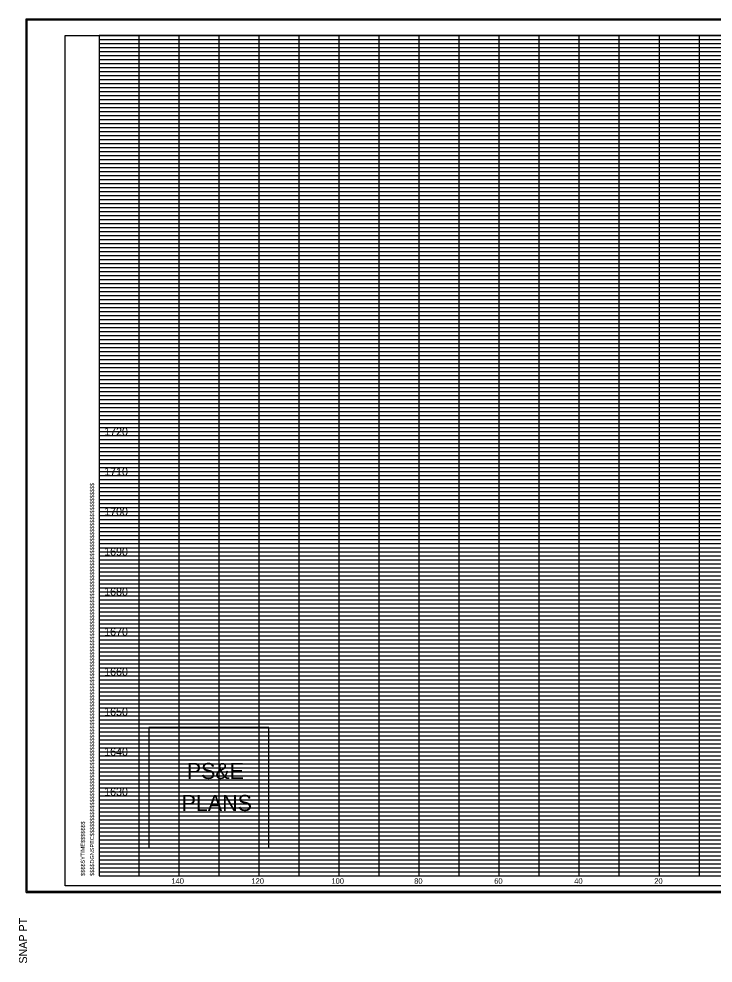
# Model space of a CAD drawing. Extents: x 980 to 2228, y 978 to 2394.
# Drawn here: x 979.9 to 1153.4, y 1788.2 to 2024.1 of the extents above; entities that cross this region are included whole.
import ezdxf

# ---------------------------------------------------------------- set-up
doc = ezdxf.new("R2010")
doc.units = 0
for name, color, linetype in [('DESIGN - SHEET - Corner Text', 7, 'Continuous'), ('DESIGN - SHEET - Light Grid', 7, 'Continuous'), ('DESIGN - SHEET - Linework', 7, 'Continuous'), ('DESIGN - SHEET - Plot Shape', 7, 'Continuous'), ('DESIGN - TYPICAL - Finished Grade and Subgrade', 7, 'Continuous')]:
    doc.layers.add(name, color=color, linetype=linetype)

# ---------------------------------------------------------------- blocks, each defined once
blk = doc.blocks.new('XSTSHT')
at = {"layer": 'DESIGN - SHEET - Light Grid'}
for p, q in [((0, 20.9), (8, 20.9)), ((0, 20.8), (8, 20.8)), ((8, 20.9), (16, 20.9)), ((8, 20.8), (16, 20.8)), ((0, 20.7), (8, 20.7)), ((0, 20.6), (8, 20.6)), ((8, 20.7), (16, 20.7)), ((8, 20.6), (16, 20.6)), ((0, 20.5), (8, 20.5)), ((0, 20.4), (8, 20.4)), ((0, 20.3), (8, 20.3)), ((8, 20.5), (16, 20.5)), ((8, 20.4), (16, 20.4)), ((8, 20.3), (16, 20.3)), ((0, 20.2), (8, 20.2)), ((0, 20.1), (8, 20.1)), ((8, 20.2), (16, 20.2)), ((8, 20.1), (16, 20.1)), ((0, 19.9), (8, 19.9)), ((8, 19.9), (16, 19.9)), ((0, 19.8), (8, 19.8)), ((0, 19.7), (8, 19.7)), ((0, 19.6), (8, 19.6)), ((8, 19.8), (16, 19.8)), ((8, 19.7), (16, 19.7)), ((8, 19.6), (16, 19.6)), ((0, 19.5), (8, 19.5)), ((0, 19.4), (8, 19.4)), ((8, 19.5), (16, 19.5)), ((8, 19.4), (16, 19.4)), ((0, 19.3), (8, 19.3)), ((0, 19.2), (8, 19.2)), ((8, 19.3), (16, 19.3)), ((8, 19.2), (16, 19.2)), ((0, 19.1), (8, 19.1)), ((0, 18.9), (8, 18.9)), ((8, 19.1), (16, 19.1)), ((8, 18.9), (16, 18.9)), ((0, 18.8), (8, 18.8)), ((0, 18.7), (8, 18.7)), ((8, 18.8), (16, 18.8)), ((8, 18.7), (16, 18.7)), ((0, 18.6), (8, 18.6)), ((0, 18.5), (8, 18.5)), ((8, 18.6), (16, 18.6)), ((8, 18.5), (16, 18.5)), ((0, 18.4), (8, 18.4)), ((0, 18.3), (8, 18.3)), ((0, 18.2), (8, 18.2)), ((8, 18.4), (16, 18.4)), ((8, 18.3), (16, 18.3)), ((8, 18.2), (16, 18.2)), ((0, 18.1), (8, 18.1)), ((8, 18.1), (16, 18.1)), ((0, 17.9), (8, 17.9)), ((0, 17.8), (8, 17.8)), ((0, 17.7), (8, 17.7)), ((8, 17.9), (16, 17.9)), ((8, 17.8), (16, 17.8)), ((8, 17.7), (16, 17.7)), ((0, 17.6), (8, 17.6)), ((0, 17.5), (8, 17.5)), ((8, 17.6), (16, 17.6)), ((8, 17.5), (16, 17.5)), ((0, 17.4), (8, 17.4)), ((0, 17.3), (8, 17.3)), ((8, 17.4), (16, 17.4)), ((8, 17.3), (16, 17.3)), ((0, 17.2), (8, 17.2)), ((0, 17.1), (8, 17.1)), ((8, 17.2), (16, 17.2)), ((8, 17.1), (16, 17.1)), ((0, 16.9), (8, 16.9)), ((0, 16.8), (8, 16.8)), ((8, 16.9), (16, 16.9)), ((8, 16.8), (16, 16.8)), ((0, 16.7), (8, 16.7)), ((0, 16.6), (8, 16.6)), ((8, 16.7), (16, 16.7)), ((8, 16.6), (16, 16.6)), ((0, 16.5), (8, 16.5)), ((0, 16.4), (8, 16.4)), ((0, 16.3), (8, 16.3)), ((8, 16.5), (16, 16.5)), ((8, 16.4), (16, 16.4)), ((8, 16.3), (16, 16.3)), ((0, 16.2), (8, 16.2)), ((0, 16.1), (8, 16.1)), ((8, 16.2), (16, 16.2)), ((8, 16.1), (16, 16.1)), ((0, 15.9), (8, 15.9)), ((8, 15.9), (16, 15.9)), ((0, 15.8), (8, 15.8)), ((0, 15.7), (8, 15.7)), ((0, 15.6), (8, 15.6)), ((8, 15.8), (16, 15.8)), ((8, 15.7), (16, 15.7)), ((8, 15.6), (16, 15.6)), ((0, 15.5), (8, 15.5)), ((0, 15.4), (8, 15.4)), ((8, 15.5), (16, 15.5)), ((8, 15.4), (16, 15.4)), ((0, 15.3), (8, 15.3)), ((0, 15.2), (8, 15.2)), ((8, 15.3), (16, 15.3)), ((8, 15.2), (16, 15.2)), ((0, 15.1), (8, 15.1)), ((0, 14.9), (8, 14.9)), ((8, 15.1), (16, 15.1)), ((8, 14.9), (16, 14.9)), ((0, 14.8), (8, 14.8)), ((0, 14.7), (8, 14.7)), ((8, 14.8), (16, 14.8)), ((8, 14.7), (16, 14.7)), ((0, 14.6), (8, 14.6)), ((0, 14.5), (8, 14.5)), ((0, 14.4), (8, 14.4)), ((8, 14.6), (16, 14.6)), ((8, 14.5), (16, 14.5)), ((8, 14.4), (16, 14.4)), ((0, 14.3), (8, 14.3)), ((0, 14.2), (8, 14.2)), ((8, 14.3), (16, 14.3)), ((8, 14.2), (16, 14.2)), ((0, 14.1), (8, 14.1)), ((8, 14.1), (16, 14.1)), ((0, 13.9), (8, 13.9)), ((0, 13.8), (8, 13.8)), ((0, 13.7), (8, 13.7)), ((8, 13.9), (16, 13.9)), ((8, 13.8), (16, 13.8)), ((8, 13.7), (16, 13.7)), ((0, 13.6), (8, 13.6)), ((0, 13.5), (8, 13.5)), ((8, 13.6), (16, 13.6)), ((8, 13.5), (16, 13.5)), ((0, 13.4), (8, 13.4)), ((0, 13.3), (8, 13.3)), ((8, 13.4), (16, 13.4)), ((8, 13.3), (16, 13.3)), ((0, 13.2), (8, 13.2)), ((0, 13.1), (8, 13.1)), ((8, 13.2), (16, 13.2)), ((8, 13.1), (16, 13.1)), ((0, 12.9), (8, 12.9)), ((0, 12.8), (8, 12.8)), ((8, 12.9), (16, 12.9)), ((8, 12.8), (16, 12.8)), ((0, 12.7), (8, 12.7)), ((0, 12.6), (8, 12.6)), ((8, 12.7), (16, 12.7)), ((8, 12.6), (16, 12.6)), ((0, 12.5), (8, 12.5)), ((0, 12.4), (8, 12.4)), ((0, 12.3), (8, 12.3)), ((8, 12.5), (16, 12.5)), ((8, 12.4), (16, 12.4)), ((8, 12.3), (16, 12.3)), ((0, 12.2), (8, 12.2)), ((0, 12.1), (8, 12.1)), ((8, 12.2), (16, 12.2)), ((8, 12.1), (16, 12.1)), ((0, 11.9), (8, 11.9)), ((0, 11.8), (8, 11.8)), ((8, 11.9), (16, 11.9)), ((8, 11.8), (16, 11.8)), ((0, 11.7), (8, 11.7)), ((0, 11.6), (8, 11.6)), ((8, 11.7), (16, 11.7)), ((8, 11.6), (16, 11.6)), ((0, 11.5), (8, 11.5)), ((0, 11.4), (8, 11.4)), ((8, 11.5), (16, 11.5)), ((8, 11.4), (16, 11.4)), ((0, 11.3), (8, 11.3)), ((0, 11.2), (8, 11.2)), ((0, 11.1), (8, 11.1)), ((8, 11.3), (16, 11.3)), ((8, 11.2), (16, 11.2)), ((8, 11.1), (16, 11.1)), ((0, 10.9), (8, 10.9)), ((8, 10.9), (16, 10.9)), ((0, 10.8), (8, 10.8)), ((0, 10.7), (8, 10.7)), ((8, 10.8), (16, 10.8)), ((8, 10.7), (16, 10.7)), ((0, 10.6), (8, 10.6)), ((0, 10.5), (8, 10.5)), ((0, 10.4), (8, 10.4)), ((8, 10.6), (16, 10.6)), ((8, 10.5), (16, 10.5)), ((8, 10.4), (16, 10.4)), ((0, 10.3), (8, 10.3)), ((0, 10.2), (8, 10.2)), ((8, 10.3), (16, 10.3)), ((8, 10.2), (16, 10.2)), ((0, 10.1), (8, 10.1)), ((8, 10.1), (16, 10.1)), ((0, 9.9), (8, 9.9)), ((0, 9.8), (8, 9.8)), ((0, 9.7), (8, 9.7)), ((8, 9.9), (16, 9.9)), ((8, 9.8), (16, 9.8)), ((8, 9.7), (16, 9.7)), ((0, 9.6), (8, 9.6)), ((0, 9.5), (8, 9.5)), ((8, 9.6), (16, 9.6)), ((8, 9.5), (16, 9.5)), ((0, 9.4), (8, 9.4)), ((0, 9.3), (8, 9.3)), ((8, 9.4), (16, 9.4)), ((8, 9.3), (16, 9.3)), ((0, 9.2), (8, 9.2)), ((0, 9.1), (8, 9.1)), ((8, 9.2), (16, 9.2)), ((8, 9.1), (16, 9.1)), ((0, 8.9), (8, 8.9)), ((0, 8.8), (8, 8.8)), ((8, 8.9), (16, 8.9)), ((8, 8.8), (16, 8.8)), ((0, 8.7), (8, 8.7)), ((0, 8.6), (8, 8.6)), ((0, 8.5), (8, 8.5)), ((8, 8.7), (16, 8.7)), ((8, 8.6), (16, 8.6)), ((8, 8.5), (16, 8.5)), ((0, 8.4), (8, 8.4)), ((0, 8.3), (8, 8.3)), ((8, 8.4), (16, 8.4)), ((8, 8.3), (16, 8.3)), ((0, 8.2), (8, 8.2)), ((0, 8.1), (8, 8.1)), ((8, 8.2), (16, 8.2)), ((8, 8.1), (16, 8.1)), ((0, 7.9), (8, 7.9)), ((0, 7.8), (8, 7.8)), ((8, 7.9), (16, 7.9)), ((8, 7.8), (16, 7.8)), ((0, 7.7), (8, 7.7)), ((0, 7.6), (8, 7.6)), ((8, 7.7), (16, 7.7)), ((8, 7.6), (16, 7.6)), ((0, 7.5), (8, 7.5)), ((0, 7.4), (8, 7.4)), ((8, 7.5), (16, 7.5)), ((8, 7.4), (16, 7.4)), ((0, 7.3), (8, 7.3)), ((0, 7.2), (8, 7.2)), ((0, 7.1), (8, 7.1)), ((8, 7.3), (16, 7.3)), ((8, 7.2), (16, 7.2)), ((8, 7.1), (16, 7.1)), ((0, 6.9), (8, 6.9)), ((8, 6.9), (16, 6.9)), ((0, 6.8), (8, 6.8)), ((0, 6.7), (8, 6.7)), ((8, 6.8), (16, 6.8)), ((8, 6.7), (16, 6.7)), ((0, 6.6), (8, 6.6)), ((0, 6.5), (8, 6.5)), ((0, 6.4), (8, 6.4)), ((8, 6.6), (16, 6.6)), ((8, 6.5), (16, 6.5)), ((8, 6.4), (16, 6.4)), ((0, 6.3), (8, 6.3)), ((0, 6.2), (8, 6.2)), ((8, 6.3), (16, 6.3)), ((8, 6.2), (16, 6.2)), ((0, 6.1), (8, 6.1)), ((0, 5.9), (8, 5.9)), ((8, 6.1), (16, 6.1)), ((8, 5.9), (16, 5.9)), ((0, 5.8), (8, 5.8)), ((0, 5.7), (8, 5.7)), ((8, 5.8), (16, 5.8)), ((8, 5.7), (16, 5.7)), ((0, 5.6), (8, 5.6)), ((0, 5.5), (8, 5.5)), ((8, 5.6), (16, 5.6)), ((8, 5.5), (16, 5.5)), ((0, 5.4), (8, 5.4)), ((0, 5.3), (8, 5.3)), ((0, 5.2), (8, 5.2)), ((8, 5.4), (16, 5.4)), ((8, 5.3), (16, 5.3)), ((8, 5.2), (16, 5.2)), ((0, 5.1), (8, 5.1)), ((8, 5.1), (16, 5.1)), ((0, 4.9), (8, 4.9)), ((0, 4.8), (8, 4.8)), ((8, 4.9), (16, 4.9)), ((8, 4.8), (16, 4.8)), ((0, 4.7), (8, 4.7)), ((0, 4.6), (8, 4.6)), ((0, 4.5), (8, 4.5)), ((8, 4.7), (16, 4.7)), ((8, 4.6), (16, 4.6)), ((8, 4.5), (16, 4.5)), ((0, 4.4), (8, 4.4)), ((0, 4.3), (8, 4.3)), ((8, 4.4), (16, 4.4)), ((8, 4.3), (16, 4.3)), ((0, 4.2), (8, 4.2)), ((0, 4.1), (8, 4.1)), ((8, 4.2), (16, 4.2)), ((8, 4.1), (16, 4.1)), ((0, 3.9), (8, 3.9)), ((0, 3.8), (8, 3.8)), ((8, 3.9), (16, 3.9)), ((8, 3.8), (16, 3.8)), ((0, 3.7), (8, 3.7)), ((0, 3.6), (8, 3.6)), ((8, 3.7), (16, 3.7)), ((8, 3.6), (16, 3.6)), ((0, 3.5), (8, 3.5)), ((0, 3.4), (8, 3.4)), ((8, 3.5), (16, 3.5)), ((8, 3.4), (16, 3.4)), ((0, 3.3), (8, 3.3)), ((0, 3.2), (8, 3.2)), ((0, 3.1), (8, 3.1)), ((8, 3.3), (16, 3.3)), ((8, 3.2), (16, 3.2)), ((8, 3.1), (16, 3.1)), ((0, 2.9), (8, 2.9)), ((8, 2.9), (16, 2.9)), ((0, 2.8), (8, 2.8)), ((0, 2.7), (8, 2.7)), ((0, 2.6), (8, 2.6)), ((8, 2.8), (16, 2.8)), ((8, 2.7), (16, 2.7)), ((8, 2.6), (16, 2.6)), ((0, 2.5), (8, 2.5)), ((0, 2.4), (8, 2.4)), ((8, 2.5), (16, 2.5)), ((8, 2.4), (16, 2.4)), ((0, 2.3), (8, 2.3)), ((0, 2.2), (8, 2.2)), ((8, 2.3), (16, 2.3)), ((8, 2.2), (16, 2.2)), ((0, 2.1), (8, 2.1)), ((0, 1.9), (8, 1.9)), ((8, 2.1), (16, 2.1)), ((8, 1.9), (16, 1.9)), ((0, 1.8), (8, 1.8)), ((0, 1.7), (8, 1.7)), ((8, 1.8), (16, 1.8)), ((8, 1.7), (16, 1.7)), ((0, 1.6), (8, 1.6)), ((0, 1.5), (8, 1.5)), ((8, 1.6), (16, 1.6)), ((8, 1.5), (16, 1.5)), ((0, 1.4), (8, 1.4)), ((0, 1.3), (8, 1.3)), ((0, 1.2), (8, 1.2)), ((8, 1.4), (16, 1.4)), ((8, 1.3), (16, 1.3)), ((8, 1.2), (16, 1.2)), ((0, 1.1), (8, 1.1)), ((8, 1.1), (16, 1.1)), ((0, 0.9), (8, 0.9)), ((0, 0.8), (8, 0.8)), ((8, 0.9), (16, 0.9)), ((8, 0.8), (16, 0.8)), ((0, 0.7), (8, 0.7)), ((0, 0.6), (8, 0.6)), ((0, 0.5), (8, 0.5)), ((8, 0.7), (16, 0.7)), ((8, 0.6), (16, 0.6)), ((8, 0.5), (16, 0.5)), ((0, 0.4), (8, 0.4)), ((0, 0.3), (8, 0.3)), ((8, 0.4), (16, 0.4)), ((8, 0.3), (16, 0.3)), ((0, 0.2), (8, 0.2)), ((0, 0.1), (8, 0.1)), ((8, 0.2), (16, 0.2)), ((8, 0.1), (16, 0.1))]:
    blk.add_line(p, q, dxfattribs=at)
at = {"layer": 'DESIGN - SHEET - Linework'}
for p, q in [((-1.823, -0.414), (-1.823, 21.414)), ((-1.823, 21.414), (32.217, 21.414)), ((1, 0), (1, 21)), ((2, 0), (2, 21)), ((3, 0), (3, 21)), ((4, 0), (4, 21)), ((5, 0), (5, 21)), ((6, 0), (6, 21)), ((7, 0), (7, 21)), ((8, 0), (8, 21)), ((9, 0), (9, 21)), ((10, 0), (10, 21)), ((11, 0), (11, 21)), ((12, 0), (12, 21)), ((13, 0), (13, 21)), ((14, 0), (14, 21)), ((15, 0), (15, 21)), ((0, 20), (28, 20)), ((0, 19), (32, 19)), ((0, 18), (32, 18)), ((0, 17), (32, 17)), ((0, 16), (32, 16)), ((0, 15), (32, 15)), ((0, 14), (32, 14)), ((0, 13), (32, 13)), ((0, 12), (32, 12)), ((0, 11), (32, 11)), ((0, 10), (32, 10)), ((0, 9), (32, 9)), ((0, 8), (32, 8)), ((0, 7), (32, 7)), ((0, 6), (32, 6)), ((0, 5), (32, 5)), ((0, 4), (32, 4)), ((0, 3), (32, 3)), ((0, 2), (32, 2)), ((0, 1), (32, 1)), ((-1.823, -0.414), (32.217, -0.414))]:
    blk.add_line(p, q, dxfattribs=at)
blk.add_lwpolyline([(0, 21), (0, 0), (32, 0), (32, 21), (0, 21)], dxfattribs=at)
at = {"layer": 'DESIGN - SHEET - Plot Shape'}
for points in [[(-1.803, 21.394), (32.197, 21.394), (32.197, -0.394), (-1.803, -0.394)], [(-0.85, 21), (32, 21), (32, -0.25), (-0.85, -0.25)]]:
    blk.add_lwpolyline(points, close=True, dxfattribs=at)
at = {"layer": 'DESIGN - SHEET - Corner Text'}
for s, height, p in [('$$$$DGNSPEC$$$$$$$$$$$$$$$$$$$$$$$$$$$$$$$$$$$$$$$$$$$$$$$$$$$$$$$$$$$$$$$$$$$$$$$$$$$$$$$$$$$$$$$$$$$$$$$$$$$$$$$$$$$$$$$$$$$', 0.100002, (-0.126, 0)), ('$$$$SYTIME$$$$$$$', 0.1, (-0.358, 0)), ('SNAP PT  ', 0.2, (-1.803, -2.194))]:
    blk.add_text(s, height=height, rotation=90, dxfattribs=at).set_placement(p)

msp = doc.modelspace()

# ---------------------------------------------------------------- linework, layer by layer
at = {"layer": 'DESIGN - SHEET - Corner Text'}
msp.add_lwpolyline([(1012.39, 1847.03), (1012.39, 1817.03), (1042.39, 1817.03), (1042.39, 1847.03)], close=True, dxfattribs=at)
at = {"layer": 'DESIGN - SHEET - Plot Shape'}
msp.add_lwpolyline([(991.5, 2020), (1320, 2020), (1320, 1807.5), (991.5, 1807.5)], close=True, dxfattribs=at)

# ---------------------------------------------------------------- block references
at = {"layer": 'DESIGN - TYPICAL - Finished Grade and Subgrade', "xscale": 10, "yscale": 10}
msp.add_blockref('XSTSHT', (1000, 1810), dxfattribs=at)

# ---------------------------------------------------------------- texts
at = {"layer": 'DESIGN - SHEET - Corner Text'}
for s, height, p in [('1720', 2, (1001.25, 1920)), ('1710', 2, (1001.25, 1910)), ('1700', 2, (1001.25, 1900)), ('1690', 2, (1001.25, 1890)), ('1680', 2, (1001.25, 1880)), ('1670', 2, (1001.25, 1870)), ('1660', 2, (1001.25, 1860)), ('1650', 2, (1001.25, 1850)), ('1640', 2, (1001.25, 1840)), ('PS&E', 4, (1021.91, 1834.2)), ('1630', 2, (1001.25, 1830)), ('PLANS', 4, (1020.63, 1826.2)), ('140', 1.4, (1018.06, 1808)), ('120', 1.4, (1038.06, 1808)), ('100', 1.4, (1058.06, 1808)), ('80', 1.4, (1078.74, 1808)), ('60', 1.4, (1098.74, 1808)), ('40', 1.4, (1118.74, 1808)), ('20', 1.4, (1138.74, 1808))]:
    msp.add_text(s, height=height, dxfattribs=at).set_placement(p)

doc.saveas('drawing.dxf')
